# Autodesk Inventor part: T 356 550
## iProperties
Company: Mayer & Müller AG Schaltgeräte
Created: 2006-03
Part Number: T 356 550
Material: 1.4301
Document SubType Name: Modeling
Designer: I.Baliuc
Description: Druckbolzen
Density: 7.86 g/cm^3
Rohabmessung: Rd VA 24
HalbzeugNorm: DIN 671
Zweck: Druckschalter Trenner
Author: T.Messerschmitt
Keywords: 380135
Revision Number: 356550
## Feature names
1. Drehung1 [Revolution]
2. Fase1 [Chamfer]
